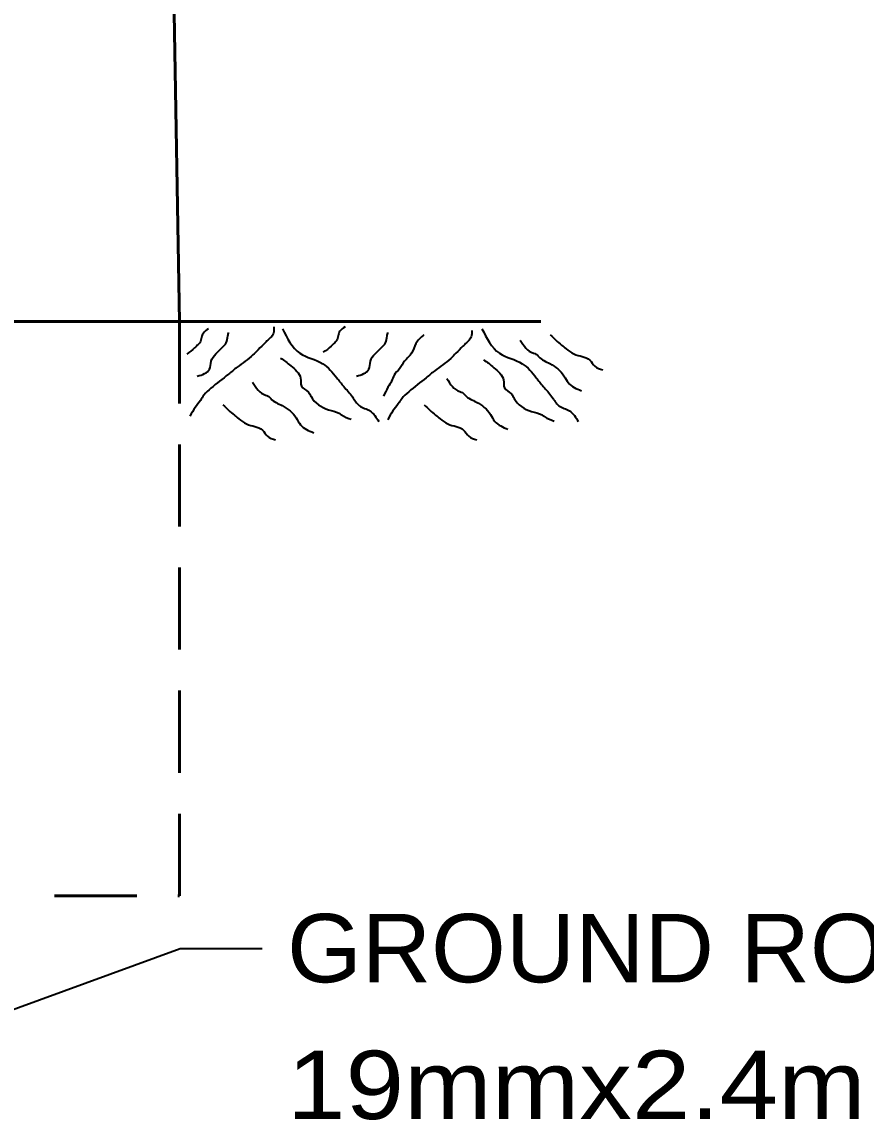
# Model space of a CAD drawing. Extents: x 14808 to 15663, y 10944 to 11488.
# Drawn here: x 15184.57 to 15221.59, y 11241.59 to 11289.76 of the extents above; entities that cross this region are included whole.
import ezdxf

# ---------------------------------------------------------------- set-up
doc = ezdxf.new("R2010")
doc.units = 0
doc.header["$LTSCALE"] = 1.2
doc.linetypes.add('MEDIUM_DASHED', pattern=[4.5, 3, -1.5])
doc.layers.add('1', color=7, linetype='Continuous', lineweight=53)

msp = doc.modelspace()

# ---------------------------------------------------------------- linework, layer by layer
at = {"layer": '1'}
for p, q in [((15188.438, 11450.597), (15191.474, 11276.623)), ((15180.319, 11276.617), (15207.319, 11276.617))]:
    msp.add_line(p, q, dxfattribs=at)
at = {"layer": '1', "linetype": 'MEDIUM_DASHED'}
for p in [(15191.474, 11276.623), (15180.601, 11251.424)]:
    msp.add_line(p, (15191.474, 11251.424), dxfattribs=at)
at = {"layer": '1', "lineweight": 35}
msp.add_lwpolyline([(15180.23, 11245.008), (15191.507, 11249.112), (15195.107, 11249.112)], dxfattribs=at)
for points in [[(15192.754, 11276.302), (15192.524, 11276.11), (15192.447, 11275.918), (15192.37, 11275.688), (15192.217, 11275.535), (15192.14, 11275.458), (15191.794, 11275.189)], [(15195.618, 11276.377), (15195.618, 11276.223), (15195.541, 11275.993), (15195.388, 11275.839), (15195.234, 11275.686), (15194.927, 11275.379), (15194.697, 11275.148), (15194.006, 11274.611), (15193.622, 11274.304), (15192.854, 11273.69), (15192.547, 11273.382), (15192.394, 11273.152), (15192.163, 11272.845), (15191.933, 11272.461)], [(15192.253, 11274.217), (15192.791, 11274.524), (15192.868, 11274.87), (15193.367, 11275.484), (15193.52, 11275.676), (15193.597, 11275.983), (15193.635, 11276.136)], [(15195.992, 11276.3), (15196.76, 11275.225), (15197.758, 11274.764), (15198.372, 11274.15), (15198.679, 11273.766), (15199.063, 11273.306), (15199.37, 11272.922), (15199.83, 11272.692), (15200.214, 11272.231)], [(15198.742, 11276.379), (15198.512, 11276.187), (15198.435, 11275.995), (15198.359, 11275.765), (15198.205, 11275.611), (15198.128, 11275.534), (15197.783, 11275.266)], [(15199.24, 11274.217), (15199.777, 11274.524), (15199.854, 11274.87), (15200.353, 11275.484), (15200.507, 11275.676), (15200.583, 11275.983), (15200.622, 11276.136)], [(15204.294, 11276.223), (15204.294, 11276.07), (15204.217, 11275.839), (15204.063, 11275.686), (15203.91, 11275.532), (15203.603, 11275.225), (15203.372, 11274.995), (15202.681, 11274.457), (15202.297, 11274.15), (15201.53, 11273.536), (15201.222, 11273.229), (15201.069, 11272.999), (15200.839, 11272.692), (15200.608, 11272.308)], [(15204.744, 11276.3), (15205.512, 11275.225), (15206.51, 11274.764), (15207.124, 11274.15), (15207.431, 11273.766), (15207.815, 11273.306), (15208.122, 11272.922), (15208.583, 11272.692), (15208.967, 11272.231)], [(15202.195, 11276.034), (15201.85, 11275.65), (15201.658, 11275.228), (15201.351, 11274.882), (15201.12, 11274.537), (15200.89, 11274.268), (15200.775, 11273.999), (15200.621, 11273.731), (15200.429, 11273.347)], [(15206.422, 11275.805), (15206.998, 11275.229), (15207.113, 11275.191), (15207.228, 11275.076), (15207.727, 11274.769), (15208.341, 11274.231), (15208.533, 11273.924), (15209.109, 11273.579)], [(15207.74, 11276.036), (15208.239, 11275.576), (15208.431, 11275.422), (15208.777, 11275.192), (15209.468, 11274.923), (15209.698, 11274.654), (15210.044, 11274.501)], [(15195.902, 11275.012), (15196.132, 11274.858), (15196.363, 11274.667), (15196.785, 11274.129), (15196.823, 11273.784), (15197.13, 11273.515), (15197.246, 11273.323), (15198.013, 11272.747), (15198.474, 11272.594), (15198.589, 11272.517), (15199.011, 11272.325)], [(15204.808, 11274.935), (15205.038, 11274.782), (15205.268, 11274.59), (15205.691, 11274.052), (15205.729, 11273.707), (15206.036, 11273.438), (15206.151, 11273.246), (15206.919, 11272.67), (15207.38, 11272.517), (15207.495, 11272.44), (15207.917, 11272.248)], [(15194.675, 11273.962), (15195.251, 11273.387), (15195.366, 11273.348), (15195.481, 11273.233), (15195.981, 11272.926), (15196.595, 11272.389), (15196.787, 11272.082), (15197.362, 11271.736)], [(15203.197, 11274.116), (15203.773, 11273.54), (15203.888, 11273.502), (15204.003, 11273.387), (15204.502, 11273.08), (15205.117, 11272.542), (15205.309, 11272.235), (15205.884, 11271.89)], [(15193.383, 11272.965), (15193.883, 11272.505), (15194.075, 11272.351), (15194.42, 11272.121), (15195.111, 11271.852), (15195.341, 11271.583), (15195.687, 11271.43)], [(15202.213, 11272.965), (15202.712, 11272.505), (15202.904, 11272.351), (15203.249, 11272.121), (15203.94, 11271.852), (15204.17, 11271.583), (15204.516, 11271.43)]]:
    msp.add_spline(points, degree=3, dxfattribs=at)

# ---------------------------------------------------------------- texts
at = {"layer": '1'}
for s, width, p in [('GROUND ROD', 1.05, (15196.196, 11247.628)), ('19mmx2.4m', 1.15, (15196.196, 11241.628))]:
    msp.add_text(s, height=3, dxfattribs=dict(at, width=width)).set_placement(p)

doc.saveas('drawing.dxf')
